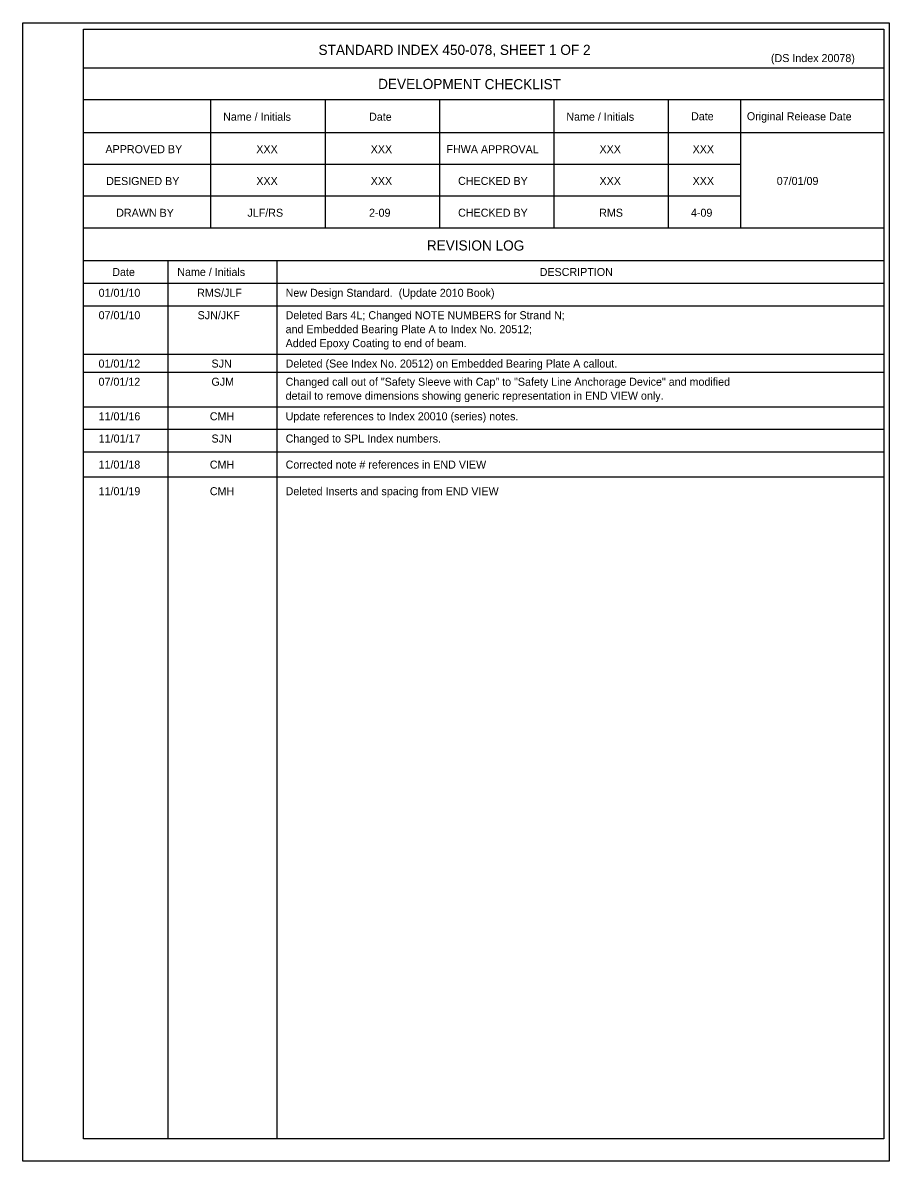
# Model space of a CAD drawing. Extents: x 1.2 to 40.7, y 0.4 to 17.4.
# Drawn here: x 29.79 to 40.7, y 2.25 to 16.59 of the extents above; entities that cross this region are included whole.
import ezdxf

# ---------------------------------------------------------------- set-up
doc = ezdxf.new("R2010")
doc.units = 0
for name, color, linetype in [('Border', 7, 'Continuous'), ('Dimension', 7, 'Continuous'), ('PlotBorder_dp', 7, 'Continuous'), ('TextStructures', 7, 'Continuous')]:
    doc.layers.add(name, color=color, linetype=linetype)

msp = doc.modelspace()

# ---------------------------------------------------------------- linework, layer by layer
at = {"layer": 'Border'}
for p, q in [((40.633, 16.015), (30.559, 16.015)), ((40.633, 15.615), (30.559, 15.615)), ((32.159, 15.615), (32.159, 14.002)), ((33.599, 15.615), (33.599, 14.002)), ((35.039, 15.615), (35.039, 14.002)), ((36.479, 15.615), (36.479, 14.002)), ((37.919, 15.615), (37.919, 14.002)), ((38.827, 15.615), (38.827, 14.002)), ((40.633, 15.202), (30.559, 15.202)), ((38.827, 14.802), (30.559, 14.802)), ((38.827, 14.402), (30.559, 14.402)), ((40.633, 14.002), (30.559, 14.002)), ((40.633, 13.588), (30.559, 13.588)), ((31.62, 13.588), (31.62, 2.534)), ((32.991, 13.588), (32.991, 2.534)), ((40.633, 13.306), (30.559, 13.306))]:
    msp.add_line(p, q, dxfattribs=at)
msp.add_lwpolyline([(30.56, 16.506), (40.633, 16.506), (40.633, 2.534), (30.56, 2.534)], close=True, dxfattribs=at)
at = {"layer": 'Dimension'}
for p, q in [((30.56, 13.024), (40.633, 13.024)), ((30.56, 12.415), (40.633, 12.415)), ((30.56, 12.186), (40.633, 12.186)), ((30.56, 11.751), (40.633, 11.751)), ((30.56, 11.471), (40.633, 11.471)), ((30.56, 11.185), (40.633, 11.185)), ((30.56, 10.872), (40.633, 10.872))]:
    msp.add_line(p, q, dxfattribs=at)
at = {"layer": 'PlotBorder_dp'}
msp.add_line((29.794, 2.254), (29.794, 2.254), dxfattribs=at)
msp.add_lwpolyline([(29.794, 16.587), (40.701, 16.587), (40.701, 2.254), (29.794, 2.254)], close=True, dxfattribs=at)

# ---------------------------------------------------------------- texts
at = {"layer": 'TextStructures'}
for s, height, p in [('STANDARD INDEX 450-078, SHEET 1 OF 2', 0.128, (33.517, 16.182)), ('(DS Index 20078)', 0.1008, (39.212, 16.092)), ('XXX', 0.1008, (32.734, 14.945)), ('XXX', 0.1008, (34.174, 14.945)), ('XXX', 0.1008, (37.054, 14.945)), ('XXX', 0.1008, (38.226, 14.945)), ('XXX', 0.1008, (32.734, 14.545)), ('XXX', 0.1008, (34.174, 14.545)), ('XXX', 0.1008, (37.054, 14.545)), ('XXX', 0.1008, (38.226, 14.545)), ('07/01/09', 0.1008, (39.285, 14.545)), ('JLF/RS', 0.1008, (32.622, 14.145)), ('2-09', 0.1008, (34.153, 14.145)), ('RMS', 0.1008, (37.05, 14.145)), ('4-09', 0.1008, (38.205, 14.145)), ('DESCRIPTION', 0.1008, (36.301, 13.399)), ('01/01/10', 0.1008, (30.749, 13.137)), ('RMS/JLF', 0.1008, (31.99, 13.137)), ('New Design Standard.  (Update 2010 Book)', 0.1008, (33.103, 13.137)), ('07/01/10', 0.1008, (30.749, 12.855)), ('SJN/JKF', 0.1008, (31.995, 12.855)), ('Deleted Bars 4L; Changed NOTE NUMBERS for Strand N;', 0.1008, (33.103, 12.855)), ('and Embedded Bearing Plate A to Index No. 20512;', 0.1008, (33.103, 12.679)), ('Added Epoxy Coating to end of beam.', 0.1008, (33.103, 12.503)), ('01/01/12', 0.1008, (30.748, 12.246)), ('SJN', 0.1008, (32.17, 12.246)), ('Deleted (See Index No. 20512) on Embedded Bearing Plate A callout.', 0.1008, (33.103, 12.246)), ('07/01/12', 0.1008, (30.748, 12.017)), ('GJM', 0.1008, (32.169, 12.017)), ('Changed call out of "Safety Sleeve with Cap" to "Safety Line Anchorage Device" and modified', 0.1008, (33.103, 12.017)), ('detail to remove dimensions showing generic representation in END VIEW only.', 0.1008, (33.103, 11.841)), ('11/01/16', 0.1008, (30.749, 11.582)), ('CMH', 0.1008, (32.149, 11.582)), ('Update references to Index 20010 (series) notes.', 0.1008, (33.103, 11.582)), ('11/01/17', 0.1008, (30.75, 11.302)), ('SJN', 0.1008, (32.17, 11.302)), ('Changed to SPL Index numbers.', 0.1008, (33.103, 11.302)), ('11/01/18', 0.1008, (30.748, 10.974)), ('CMH', 0.1008, (32.149, 10.974)), ('Corrected note # references in END VIEW', 0.1008, (33.103, 10.974)), ('11/01/19', 0.1008, (30.749, 10.639)), ('CMH', 0.1008, (32.149, 10.639)), ('Deleted Inserts and spacing from END VIEW', 0.1008, (33.103, 10.639))]:
    msp.add_text(s, height=height, dxfattribs=at).set_placement(p)
for s, height, p in [('DEVELOPMENT CHECKLIST', 0.128, (34.267, 15.754)), ('Name / Initials', 0.1008, (32.316, 15.355)), ('Date', 0.1008, (34.153, 15.354)), ('Name / Initials', 0.1008, (36.636, 15.355)), ('Date', 0.1008, (38.206, 15.36)), ('Original Release Date', 0.1008, (38.909, 15.36)), ('APPROVED BY', 0.1008, (30.835, 14.946)), ('FHWA APPROVAL', 0.1008, (35.127, 14.946)), ('DESIGNED BY', 0.1008, (30.844, 14.545)), ('CHECKED BY', 0.1008, (35.274, 14.546)), ('DRAWN BY', 0.1008, (30.97, 14.145)), ('CHECKED BY', 0.1008, (35.274, 14.146)), ('REVISION LOG', 0.128, (34.88, 13.721)), ('Date', 0.1008, (30.921, 13.399)), ('Name / Initials', 0.1008, (31.739, 13.4))]:
    msp.add_text(s, height=height, rotation=359.8756, dxfattribs=at).set_placement(p)

doc.saveas('drawing.dxf')
